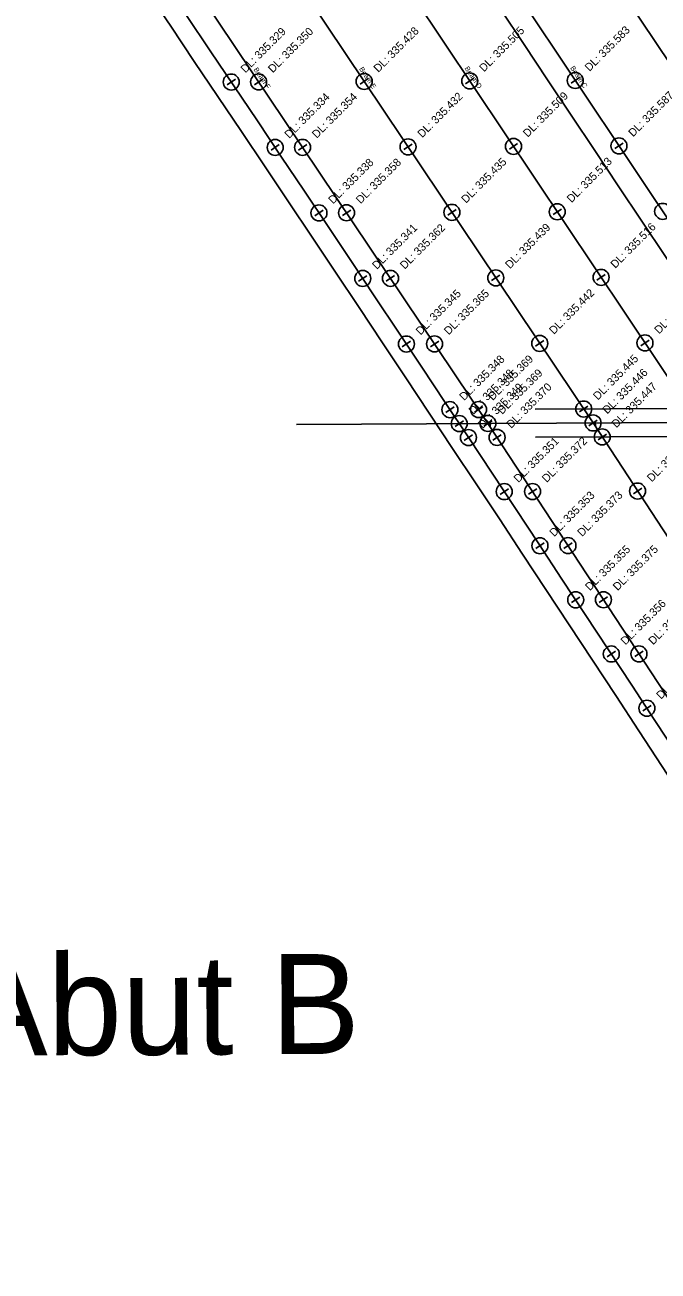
# Model space of a CAD drawing. Extents: x 1524497 to 1524592, y 1103688 to 1103812.
# Drawn here: x 1524529.69 to 1524545.51, y 1103718.69 to 1103749.84 of the extents above; entities that cross this region are included whole.
import ezdxf

# ---------------------------------------------------------------- set-up
doc = ezdxf.new("R2010")
doc.units = 0
doc.layers.add('Level 1', color=7, linetype='Continuous')

msp = doc.modelspace()

# ---------------------------------------------------------------- linework, layer by layer
at = {"layer": 'Level 1'}
for p, q in [((1524529.816, 1103756.923), (1524541.257, 1103739.876)), ((1524532.464, 1103756.935), (1524543.885, 1103739.888)), ((1524535.113, 1103756.948), (1524546.512, 1103739.9)), ((1524537.761, 1103756.96), (1524549.14, 1103739.912)), ((1524540.409, 1103756.972), (1524551.767, 1103739.924)), ((1524534.947, 1103748.481), (1524534.739, 1103748.342)), ((1524535.423, 1103748.345), (1524535.63, 1103748.484)), ((1524538.06, 1103748.357), (1524538.268, 1103748.496)), ((1524540.698, 1103748.37), (1524540.906, 1103748.509)), ((1524543.336, 1103748.382), (1524543.544, 1103748.521)), ((1524539.156, 1103746.722), (1524539.364, 1103746.861)), ((1524541.792, 1103746.734), (1524542, 1103746.873)), ((1524544.428, 1103746.746), (1524544.636, 1103746.885)), ((1524536.043, 1103746.846), (1524535.836, 1103746.706)), ((1524536.52, 1103746.709), (1524536.728, 1103746.849)), ((1524537.139, 1103745.209), (1524536.931, 1103745.07)), ((1524537.619, 1103745.073), (1524537.827, 1103745.212)), ((1524540.253, 1103745.085), (1524540.46, 1103745.224)), ((1524542.886, 1103745.097), (1524543.094, 1103745.236)), ((1524538.232, 1103743.57), (1524538.024, 1103743.432)), ((1524538.718, 1103743.435), (1524538.926, 1103743.574)), ((1524541.35, 1103743.447), (1524541.558, 1103743.586)), ((1524543.982, 1103743.459), (1524544.19, 1103743.598)), ((1524539.323, 1103741.931), (1524539.115, 1103741.793)), ((1524539.818, 1103741.795), (1524540.026, 1103741.935)), ((1524542.448, 1103741.808), (1524542.656, 1103741.947)), ((1524545.078, 1103741.82), (1524545.286, 1103741.959)), ((1524540.412, 1103740.29), (1524540.204, 1103740.152)), ((1524540.919, 1103740.155), (1524541.127, 1103740.294)), ((1524554.382, 1103740.286), (1524542.44, 1103740.231)), ((1524543.547, 1103740.167), (1524543.755, 1103740.306)), ((1524560.354, 1103739.964), (1524536.471, 1103739.853)), ((1524540.644, 1103739.941), (1524540.435, 1103739.803)), ((1524540.644, 1103739.941), (1524540.435, 1103739.803)), ((1524541.153, 1103739.806), (1524541.361, 1103739.945)), ((1524541.153, 1103739.807), (1524541.362, 1103739.944)), ((1524541.257, 1103739.876), (1524550.726, 1103725.427)), ((1524543.78, 1103739.819), (1524543.989, 1103739.956)), ((1524543.781, 1103739.818), (1524543.989, 1103739.957)), ((1524543.885, 1103739.888), (1524553.337, 1103725.439)), ((1524540.875, 1103739.592), (1524540.667, 1103739.454)), ((1524541.381, 1103739.458), (1524541.591, 1103739.595)), ((1524554.385, 1103739.586), (1524542.444, 1103739.531)), ((1524544.008, 1103739.47), (1524544.218, 1103739.607)), ((1524541.77, 1103738.241), (1524541.561, 1103738.103)), ((1524542.267, 1103738.107), (1524542.476, 1103738.244)), ((1524544.892, 1103738.119), (1524545.102, 1103738.256)), ((1524542.663, 1103736.889), (1524542.454, 1103736.751)), ((1524543.153, 1103736.754), (1524543.362, 1103736.891)), ((1524543.555, 1103735.535), (1524543.346, 1103735.398)), ((1524544.04, 1103735.401), (1524544.249, 1103735.538)), ((1524544.445, 1103734.181), (1524544.236, 1103734.044)), ((1524544.927, 1103734.047), (1524545.137, 1103734.185)), ((1524545.335, 1103732.827), (1524545.126, 1103732.69))]:
    msp.add_line(p, q, dxfattribs=at)
for points in [[(1524541.317, 1103739.785), (1524541.31, 1103739.91), (1524541.257, 1103739.876)], [(1524543.944, 1103739.797), (1524543.937, 1103739.922), (1524543.885, 1103739.888)]]:
    msp.add_lwpolyline(points, dxfattribs=at)
for centre in [(1524534.843, 1103748.412), (1524535.527, 1103748.415), (1524538.164, 1103748.427), (1524540.802, 1103748.439), (1524543.44, 1103748.451), (1524535.94, 1103746.776), (1524536.624, 1103746.779), (1524539.26, 1103746.791), (1524541.896, 1103746.803), (1524544.532, 1103746.816), (1524537.035, 1103745.139), (1524537.723, 1103745.142), (1524540.357, 1103745.154), (1524542.99, 1103745.167), (1524545.624, 1103745.179), (1524538.128, 1103743.501), (1524538.822, 1103743.504), (1524541.454, 1103743.516), (1524544.086, 1103743.529), (1524539.219, 1103741.862), (1524539.922, 1103741.865), (1524542.552, 1103741.877), (1524545.182, 1103741.889), (1524540.308, 1103740.221), (1524541.023, 1103740.225), (1524543.651, 1103740.237), (1524540.54, 1103739.872), (1524540.54, 1103739.872), (1524541.257, 1103739.876), (1524541.257, 1103739.876), (1524543.885, 1103739.888), (1524543.885, 1103739.888), (1524540.771, 1103739.523), (1524541.486, 1103739.527), (1524544.113, 1103739.539), (1524541.665, 1103738.172), (1524542.372, 1103738.175), (1524544.997, 1103738.187), (1524542.558, 1103736.82), (1524543.258, 1103736.823), (1524543.45, 1103735.467), (1524544.145, 1103735.47), (1524544.341, 1103734.113), (1524545.032, 1103734.116), (1524545.23, 1103732.758)]:
    msp.add_circle(centre, 0.2, dxfattribs=at)
for radius, start, end in [(1736, 33.735131, 35.977852), (1736, 33.735131, 35.977852), (1736, 33.735131, 35.977852), (1736, 33.735131, 35.977852), (1736, 33.735131, 35.977852), (1736, 33.735131, 35.977852), (1736, 33.735131, 35.977852), (1736, 33.735131, 35.977852), (1729.4, 33.735131, 35.977852), (1729.4, 33.735131, 35.977852), (1729.4, 33.735131, 35.977852), (1729.4, 33.735131, 35.977852), (1729.4, 33.735131, 35.977852), (1729.4, 33.735131, 35.977852), (1729.4, 33.735131, 35.977852), (1729.4, 33.735131, 35.977852), (1728.92, 33.735131, 35.977852), (1728.92, 33.735131, 35.977852), (1728.92, 33.735131, 35.977852), (1728.92, 33.735131, 35.977852), (1728.92, 33.735131, 35.977852), (1728.92, 33.735131, 35.977852), (1728.92, 33.735131, 35.977852), (1728.92, 33.735131, 35.977852), (1736, 31.492411, 33.735131), (1736, 31.492411, 33.735131), (1736, 31.492411, 33.735131), (1736, 31.492411, 33.735131), (1736, 31.492411, 33.735131), (1736, 31.492411, 33.735131), (1736, 31.492411, 33.735131), (1736, 31.492411, 33.735131), (1729.4, 31.492411, 33.735131), (1729.4, 31.492411, 33.735131), (1729.4, 31.492411, 33.735131), (1729.4, 31.492411, 33.735131), (1729.4, 31.492411, 33.735131), (1729.4, 31.492411, 33.735131), (1729.4, 31.492411, 33.735131), (1729.4, 31.492411, 33.735131), (1728.92, 31.492411, 33.735131), (1728.92, 31.492411, 33.735131), (1728.92, 31.492411, 33.735131), (1728.92, 31.492411, 33.735131), (1728.92, 31.492411, 33.735131), (1728.92, 31.492411, 33.735131), (1728.92, 31.492411, 33.735131), (1728.92, 31.492411, 33.735131)]:
    msp.add_arc((1523099.068, 1102784.371), radius, start, end, dxfattribs=at)

# ---------------------------------------------------------------- texts
for s, height, rotation, p in [('DL: 335.329', 0.2, 45, (1524535.196, 1103748.624)), ('DL: 335.350', 0.2, 45, (1524535.88, 1103748.627)), ('DL: 335.428', 0.2, 45, (1524538.518, 1103748.639)), ('DL: 335.505', 0.2, 45, (1524541.156, 1103748.651)), ('DL: 335.583', 0.2, 45, (1524543.793, 1103748.663)), ('Beam F', 0.125, 303.8659, (1524535.394, 1103748.724)), ('Beam E', 0.125, 303.818, (1524538.031, 1103748.738)), ('Beam D', 0.125, 303.77, (1524540.668, 1103748.751)), ('Beam C', 0.125, 303.722, (1524543.307, 1103748.763)), ('DL: 335.334', 0.2, 45, (1524536.293, 1103746.988)), ('DL: 335.354', 0.2, 45, (1524536.978, 1103746.991)), ('DL: 335.432', 0.2, 45, (1524539.614, 1103747.003)), ('DL: 335.509', 0.2, 45, (1524542.249, 1103747.016)), ('DL: 335.587', 0.2, 45, (1524544.885, 1103747.028)), ('DL: 335.338', 0.2, 45, (1524537.388, 1103745.351)), ('DL: 335.358', 0.2, 45, (1524538.076, 1103745.354)), ('DL: 335.435', 0.2, 45, (1524540.71, 1103745.367)), ('DL: 335.513', 0.2, 45, (1524543.344, 1103745.379)), ('DL: 335.341', 0.2, 45, (1524538.481, 1103743.713)), ('DL: 335.362', 0.2, 45, (1524539.176, 1103743.716)), ('DL: 335.439', 0.2, 45, (1524541.807, 1103743.729)), ('DL: 335.516', 0.2, 45, (1524544.439, 1103743.741)), ('DL: 335.345', 0.2, 45, (1524539.573, 1103742.074)), ('DL: 335.365', 0.2, 45, (1524540.276, 1103742.077)), ('DL: 335.442', 0.2, 45, (1524542.906, 1103742.089)), ('DL: 335.519', 0.2, 45, (1524545.535, 1103742.101)), ('DL: 335.348', 0.2, 45, (1524540.662, 1103740.433)), ('DL: 335.369', 0.2, 45, (1524541.377, 1103740.437)), ('DL: 335.445', 0.2, 45, (1524544.004, 1103740.449)), ('DL: 335.446', 0.2, 45, (1524544.238, 1103740.1)), ('DL: 335.446', 0.2, 45, (1524544.238, 1103740.1)), ('DL: 335.348', 0.2, 45, (1524540.893, 1103740.084)), ('DL: 335.348', 0.2, 45, (1524540.893, 1103740.084)), ('DL: 335.369', 0.2, 45, (1524541.611, 1103740.088)), ('DL: 335.369', 0.2, 45, (1524541.611, 1103740.088)), ('DL: 335.349', 0.2, 45, (1524541.124, 1103739.735)), ('DL: 335.370', 0.2, 45, (1524541.84, 1103739.739)), ('DL: 335.447', 0.2, 45, (1524544.467, 1103739.751)), ('DL: 335.351', 0.2, 45, (1524542.019, 1103738.384)), ('DL: 335.372', 0.2, 45, (1524542.725, 1103738.387)), ('DL: 335.448', 0.2, 45, (1524545.351, 1103738.4)), ('DL: 335.353', 0.2, 45, (1524542.912, 1103737.032)), ('DL: 335.373', 0.2, 45, (1524543.611, 1103737.035)), ('DL: 335.355', 0.2, 45, (1524543.804, 1103735.679)), ('DL: 335.375', 0.2, 45, (1524544.498, 1103735.682)), ('DL: 335.356', 0.2, 45, (1524544.694, 1103734.325)), ('DL: 335.376', 0.2, 45, (1524545.386, 1103734.328)), ('DL: 335.358', 0.2, 45, (1524545.584, 1103732.97)), ('Abut B', 2.5, 0.265, (1524528.026, 1103724.072))]:
    msp.add_text(s, height=height, rotation=rotation, dxfattribs=at).set_placement(p)

doc.saveas('drawing.dxf')
